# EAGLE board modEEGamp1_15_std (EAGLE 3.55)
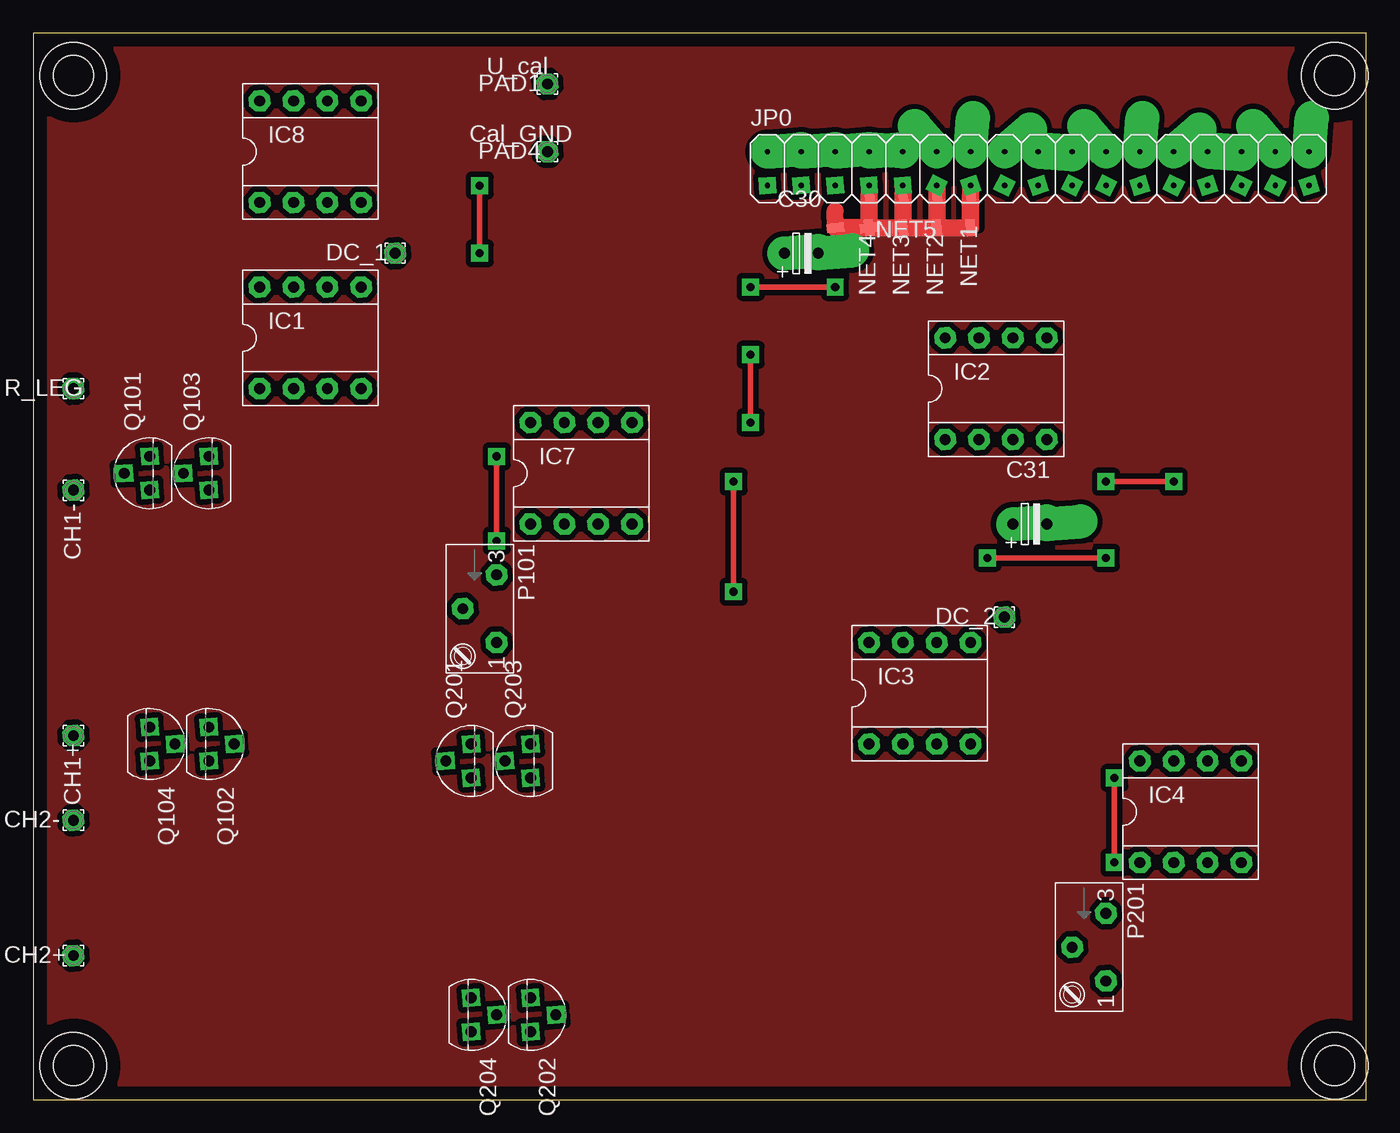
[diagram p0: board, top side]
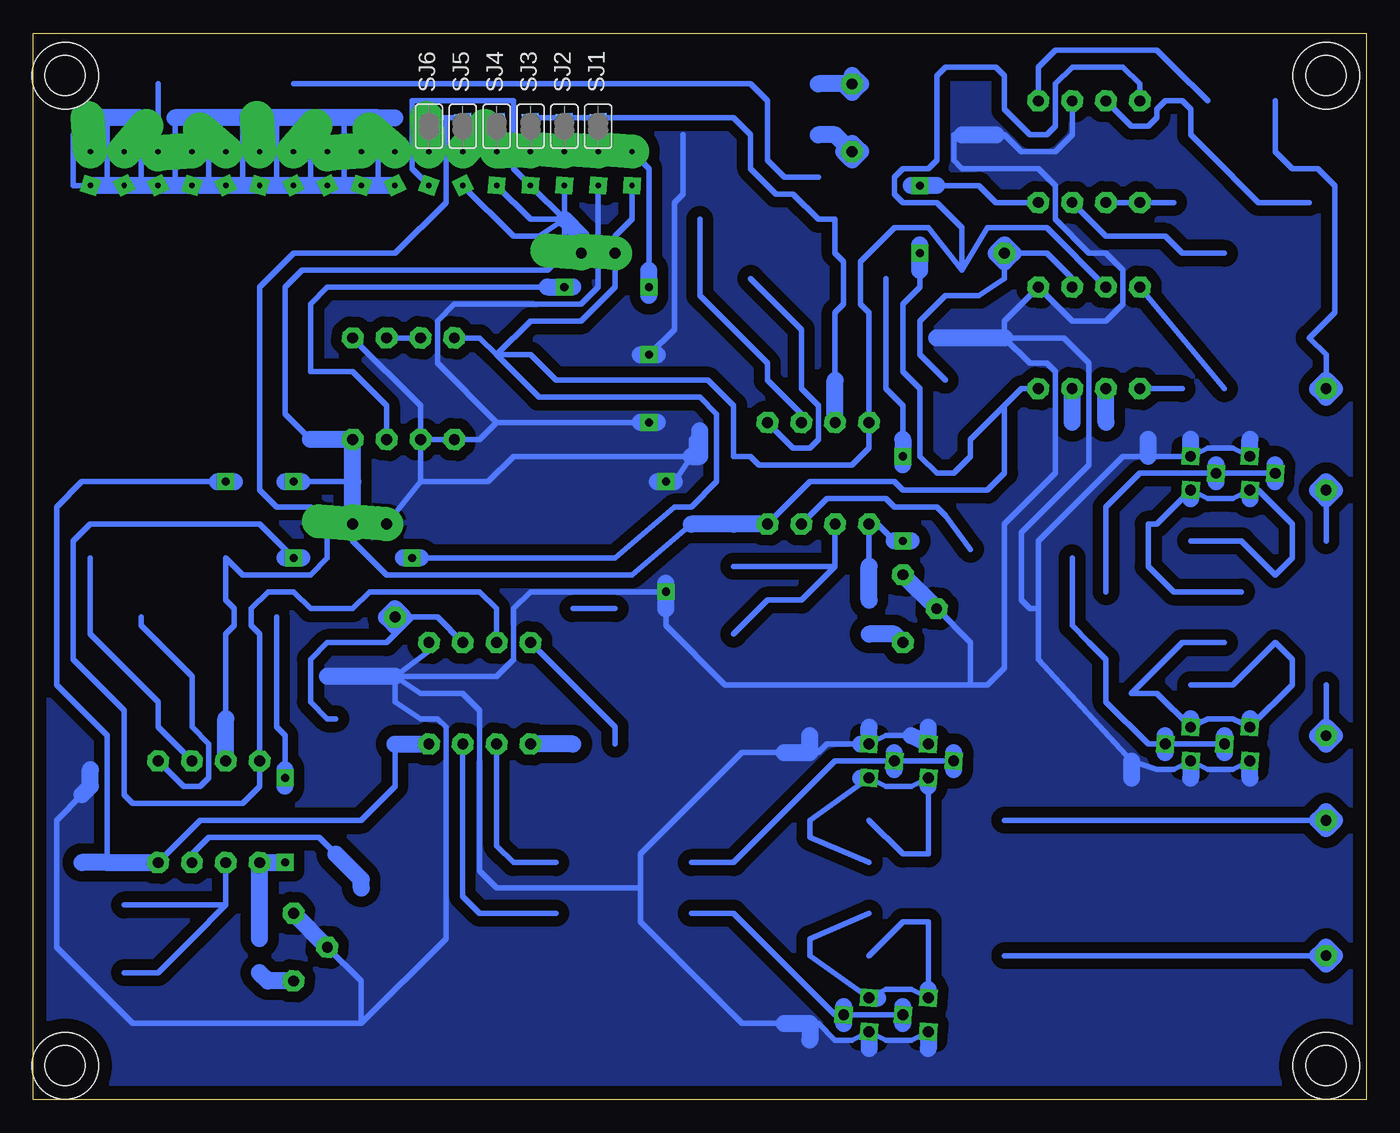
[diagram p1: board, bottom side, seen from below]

Size 100 x 80 mm. Coordinates in mm from the lower left corner, seen from the top.
Outline: 0,0 100,0 100,80 0,80 0,0
Copper layers used: Top, Bottom
Holes 3 mm at 3.01,2.54 3.01,76.83 97.62,2.54 97.62,76.83
Holes 5 mm at 3.01,76.83 97.62,76.83 3.01,2.54 97.62,2.54

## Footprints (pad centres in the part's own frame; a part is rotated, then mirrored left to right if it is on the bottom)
-2,5 = drill 0.813 pad 2.54 offset:  -1.27,0;  1.27,0
6/0,8 = drill 0.813 pad 1.6 octagon:  0,0
P-08 = drill 0.813 pad 1.6 octagon:  -3.81,-3.81;  -1.27,-3.81;  3.81,3.81;  1.27,3.81;  1.27,-3.81;  3.81,-3.81;  -1.27,3.81;  -3.81,3.81
17Y = drill 0.406 pad 1.27 square:  -20.32,-1.27;  -17.78,-1.27;  -15.24,-1.27;  -12.7,-1.27;  -10.16,-1.27;  -7.62,-1.27;  -5.08,-1.27;  -2.54,-1.27;  0,-1.27;  2.54,-1.27;  5.08,-1.27;  7.62,-1.27;  10.16,-1.27;  12.7,-1.27;  15.24,-1.27;  17.78,-1.27;  20.32,-1.27 | drill 0.406 pad 2.54 offset:  -20.32,1.27;  -17.78,1.27;  -15.24,1.27;  -12.7,1.27;  -10.16,1.27;  -7.62,1.27;  -5.08,1.27;  -2.54,1.27;  0,1.27;  2.54,1.27;  5.08,1.27;  7.62,1.27;  10.16,1.27;  12.7,1.27;  15.24,1.27;  17.78,1.27;  20.32,1.27
TCPL_T = smd 0.635 x 1.27 rotated 97:  -1.27,0;  1.27,0
4Y = drill 0.813 pad 1.6 octagon:  2.54,1.27;  -2.54,1.27;  0,-1.27
92 = drill 0.813 pad 1.27 square:  1.27,0;  0,1.905;  -1.27,0
5X5 = smd 0.635 x 1.27 rotated 4.3:  -0.635,0 | smd 0.635 x 1.27 rotated 4.4:  0.635,0

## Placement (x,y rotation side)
C3  10nF  [5-Y]  79.21,52.07 270 top
C13  0.1uFcer  [5-Y]  73.5,46.35 0 top
C21  0.1uFcer  [5-Y]  65.24,53.34 90 top
C22  10nFcer  [5-Y]  57.62,66.04 0 top
C28  1nF_200V  [5-Y]  9.36,71.12 0 top
C30  47æ  [-2,5]  57.62,63.5 0 top
C31  47æ_tant_500mO  [-2,5]  74.77,43.18 0 top
C36  1n_200V  [5-Y]  9.36,74.93 0 top
C41  0.1uFcer  [5-Y]  27.77,69.85 90 top
C42  0.1uFcer  [5-XY]  30.31,74.93 90 top
C101  10pF_cer  [5-Y]  6.82,36.83 90 top
C102  100pF_cer  [5-Y]  17.61,27.94 270 top
C103  100pF_cer  [5-Y]  16.34,45.72 270 top
C104  0.1uFcer  [5-Y]  27.14,54.61 90 top
C105  0.1uFcer  [5-Y]  30.31,59.69 270 top
C106  1æF  [5-10C]  31.58,48.9 90 top
C107  1nF  [5-Y]  39.84,37.47 180 top
C108  1uF  [5-10C]  41.11,61.59 0 top
C109  1nF  [5-Y]  42.38,53.98 180 top
C110  0.1uFcer  [5-Y]  50.63,45.72 90 top
C111  0.1uFcer  [5-X]  47.46,45.72 90 top
C201  10pF_cer  [5-Y]  32.85,15.88 90 top
C202  100pF_cer  [5-Y]  41.74,8.26 270 top
C203  100pF_cer  [5-Y]  41.74,23.5 270 top
C204  0.1uFcer  [5-Y]  72.86,29.21 90 top
C205  0.1uFcer  [5-Y]  76.03,34.29 270 top
C206  1æF  [5-10C]  77.3,23.5 90 top
C207  1nF  [5-Y]  85.56,12.06 180 top
C208  1uF  [5-10C]  86.83,36.2 0 top
C209  1nF  [5-Y]  88.1,28.57 180 top
C210  0.1uFcer  [5-X]  96.36,20.32 90 top
C211  0.1uFcer  [5-X]  93.18,20.32 90 top
CH1+  [6/0,8]  3.01,27.3 90 top
CH1-  [6/0,8]  3.01,45.72 90 top
CH2+  [6/0,8]  3.01,10.79 0 top
CH2-  [6/0,8]  3.01,20.95 0 top
DC_1  [6/0,8]  27.14,63.5 0 top
DC_2  [6/0,8]  72.86,36.2 0 top
IC1  INA114BP  [P-08]  20.79,57.15 0 top
IC2  TLC277CP  [P-08]  72.22,53.34 0 top
IC3  INA114BP  [P-08]  66.51,30.48 0 top
IC4  TLC277P  [P-08]  86.83,21.59 0 top
IC7  TLC277P  [P-08]  41.11,46.99 0 top
IC8  TLC277P  [P-08]  20.79,71.12 0 top
JP0  PINHD-2X17  [17Y]  75.4,69.85 0 top
NET1  NETCPL_T  [TCPL_T]  70.32,66.67 90 top
NET2  NETCPL_T  [TCPL_T]  67.78,66.67 90 top
NET3  NETCPL_T  [TCPL_T]  65.24,66.67 90 top
NET4  NETCPL_T  [TCPL_T]  62.7,66.67 90 top
NET5  NETCPL_T  [TCPL_T]  61.43,65.41 180 top
P101  10k  [4Y]  33.49,36.83 270 top
P201  10k  [4Y]  79.21,11.43 270 top
PAD1  U_cal  [6/0,8]  38.57,76.2 0 top
PAD4  Cal_GND  [6/0,8]  38.57,71.12 0 top
Q101  BC547  [92]  8.73,46.99 90 top
Q102  BC547  [92]  13.17,26.67 270 top
Q103  BC557  [92]  13.17,46.99 90 top
Q104  BC557  [92]  8.73,26.67 270 top
Q201  BC547  [92]  32.85,25.4 90 top
Q202  BC547  [92]  37.3,6.35 270 top
Q203  BC557  [92]  37.3,25.4 90 top
Q204  BC557  [92]  32.85,6.35 270 top
R25  510k  [10]  4.28,62.23 90 top
R26  10k  [10]  46.19,72.39 0 top
R27  10k  [10]  14.44,72.39 270 top
R33  2.0M_1%  [10Q]  85.56,76.2 0 top
R34  100_1%  [10Q]  46.19,69.22 180 top
R42  10k  [10Q]  46.19,76.2 0 top
R101  2k2  [10]  8.09,41.91 0 top
R102  2k2  [10]  8.09,31.11 0 top
R103  2k2  [10]  14.44,38.1 0 top
R104  2k2  [10]  15.71,34.29 0 top
R105  2k2  [10]  19.52,45.72 90 top
R106  2k2  [10]  22.06,45.72 90 top
R107  2k7_1%  [10Q]  13.81,58.42 90 top
R108  2k7_1%  [10Q]  10.63,58.42 90 top
R109  1meg  [10Q]  29.68,36.2 90 top
R110  1k  [10]  42.38,34.92 0 top
R111  200k  [10Q]  42.38,40.01 180 top
R112  1meg  [10Q]  37.3,57.15 0 top
R113  1k  [10]  50,55.24 90 top
R114  27k  [10Q]  44.92,66.04 180 top
R201  2k2  [10]  32.22,20.95 0 top
R202  2k2  [10]  32.22,10.79 0 top
R203  2k2  [10]  42.38,17.78 0 top
R204  2k2  [10]  42.38,13.97 0 top
R205  2k2  [10]  55.71,17.78 0 top
R206  2k2  [10]  55.71,13.97 0 top
R207  2k7_1%  [10Q]  59.52,31.75 90 top
R208  2k7_1%  [10Q]  56.35,31.75 90 top
R209  1meg  [10Q]  75.4,10.79 90 top
R210  1k  [10]  88.1,9.53 0 top
R211  200k  [10Q]  88.1,14.61 180 top
R212  1meg  [10Q]  83.02,31.75 0 top
R213  1k  [10]  95.72,29.84 90 top
R214  27k  [10Q]  90.64,40.64 180 top
R_LEG  [6/0,8]  3.01,53.34 0 top
SJ1  SJ  [5X5]  57.62,73.03 90 bottom
SJ2  SJ  [5X5]  60.16,73.03 90 bottom
SJ3  SJ  [5X5]  62.7,73.03 90 bottom
SJ4  SJ  [5X5]  65.24,73.03 90 bottom
SJ5  SJ  [5X5]  67.78,73.03 90 bottom
SJ6  SJ  [5X5]  70.32,73.03 90 bottom

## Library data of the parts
C3 C13 C21 C22 C28 C30 C31 C36 C41 C42 C101-C111 C201-C211 R25-R27 R33 R34 R42 R101-R114 R201-R214 = DISCRETE
CH1+ CH1- CH2+ CH2- DC_1 DC_2 PAD1 PAD4 R_LEG = WIREPAD
IC1-IC4 IC7 IC8 = BURR
JP0 = PINHEAD
NET1-NET5 = SPECIAL
P101 P201 = TRIMPOT
Q101 Q102 Q201 Q202 = NPN
Q103 Q104 Q203 Q204 = pnp
SJ1-SJ6 = JUMPER

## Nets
2.0V: C3. IC2. JP0.
+5V/2: C21. C22. C30. C42. C105. C111. C205. C211. IC1. IC2. IC3. IC4. IC7. IC8. JP0.
+5V/3: JP0.
ADIN0: C109. IC7. R114. SJ1. SJ2. SJ3.
ADIN1: C209. IC4. R214. SJ4. SJ5. SJ6.
AGND: C3. C13. C22. C30. C31. C41. C104. C110. C111. C204. C210. C211. IC1. IC2. IC3. IC4. IC7. IC8. JP0. NET1. NET2. NET3. NET4. NET5.
AGND2: NET1. NET2. NET3. NET4. NET5.
GND2: JP0.
N$1: IC3. R207.
N$2: IC3. R208.
N$3: R207. R208.
N$4: C206. DC_2. IC3.
N$5: IC3. R205.
N$6: CH1-. R101.
N$7: IC3. R206.
N$8: Q201. Q203. R203. R205.
N$9: C201. C203. Q201. Q203. R201. R203.
N$10: Q202. Q204. R204. R206.
N$11: CH1+. R102.
N$12: IC8. R107. R108.
N$13: C201. C202. Q202. Q204. R202. R204.
N$14: IC1. R107.
N$15: CH2-. R201.
N$16: CH2+. R202.
N$17: C206. IC4. R209.
N$18: C207. IC4. R210. R211.
N$19: P201. R210.
N$20: IC1. R108.
N$21: IC1. R105.
N$22: C207. C208. IC4. R211.
N$23: C208. IC4. R212.
N$24: C209. IC4. R213. R214.
N$25: C106. DC_1. IC1.
N$26: JP0. SJ1.
N$27: IC1. R106.
N$28: C106. IC7. R109.
N$29: Q101. Q103. R103. R105.
N$30: PAD4. R26.
N$31: JP0. SJ2.
N$32: C101. C103. Q101. Q103. R101. R103.
N$33: C28. IC8. R25.
N$34: R33. R34. R42.
N$35: JP0. SJ3.
N$36: JP0. SJ4.
N$37: JP0. SJ5.
N$38: C107. IC7. R110. R111.
N$39: Q102. Q104. R104. R106.
N$40: P101. R110.
N$41: C36. IC8. R27.
N$42: C107. C108. IC7. R111.
N$43: C101. C102. Q102. Q104. R102. R104.
N$44: JP0. SJ6.
N$48: PAD1. R42.
N$50: C108. IC7. R112.
N$51: C109. IC7. R113. R114.
N$52: IC8. R27.
N$53: IC2.
PWM: JP0. R33.
R_LEG: C28. C36. R25. R_LEG.
VREF/2: C13. C21. C31. C41. C42. C102. C103. C104. C105. C110. C202. C203. C204. C205. C210. IC1. IC2. IC3. IC8. JP0. P101. P201. Q101. Q102. Q103. Q104. Q201. Q202. Q203. Q204. R26. R34. R109. R112. R113. R209. R212. R213.

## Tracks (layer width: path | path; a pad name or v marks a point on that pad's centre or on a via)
2.0V  (via drill 0.61 pad 1.27)
  Top 0.406: v53.81,60.96 v60.16,60.96
  Bottom 0.406: 73.5,49.53 73.5,52.07 76.03,54.61 79.21,54.61 79.21,59.69 77.94,60.96 61.43,60.96 v60.16,60.96 | v53.81,60.96 53.81,62.23 53.81,69.85 55.08,71.12
  Bottom 1.27: 53.81,60.33 53.81,62.23 | 61.43,60.96 59.52,60.96
+5V/2  (via drill 0.61 pad 1.27)
  Top 0.406: v71.59,40.64 v80.48,40.64
  Bottom 0.406: 55.08,68.58 55.08,66.04 56.35,64.77 56.35,63.5 56.35,60.96 58.89,58.42 62.7,58.42 65.24,55.88 | 19.52,60.96 23.96,65.41 28.41,65.41 30.31,62.23 | 65.24,55.88 66.51,57.15 IC2. | IC8. 16.98,76.2 18.25,77.47 22.06,77.47 23.33,76.2 23.33,73.03 23.96,72.39 25.23,72.39 27.14,74.3 27.14,76.83 27.77,77.47 30.31,77.47 31.58,77.47 32.22,76.83 32.22,70.48 32.85,69.85 34.76,69.85 35.39,69.22 35.39,67.94 34.76,67.31 32.22,67.31 30.31,65.41 30.31,62.23 | 30.31,62.23 32.85,65.41 35.39,65.41 37.94,62.87 37.94,59.69 37.3,59.05 IC7. 37.3,48.9 38.57,47.62 45.55,47.62 46.19,48.26 47.46,48.26 47.46,52.07 49.37,53.98 60.8,53.98 62.7,55.88 65.24,55.88 | 65.24,34.29 65.24,36.83 66.51,38.1 74.77,38.1 76.03,36.83 79.21,36.83 80.48,38.1 82.39,38.1 83.66,36.83 83.66,35.56 83.02,34.92 IC4. 83.02,23.5 84.29,22.23 92.55,22.23 93.18,22.86 93.18,29.21 96.99,33.02 96.99,41.91 95.72,43.18 83.02,43.18 v80.48,40.64 | 65.24,55.88 62.06,52.7 50,52.7 48.73,51.44 48.73,46.35 50.63,44.45 51.91,44.45 56.35,40.64 v71.59,40.64
  Bottom 1.27: 70.95,40.64 v71.59,40.64 72.22,40.64 | 79.84,40.64 v80.48,40.64 81.11,40.64
ADIN0
  Bottom 0.406: SJ3. SJ2. SJ1. 47.46,73.66 46.19,72.39 46.19,69.85 44.28,67.94 43.02,67.94 41.11,66.04 39.84,66.04 39.84,63.5 39.2,62.87 39.2,59.69 39.84,59.05 39.84,53.98 39.84,50.8
  Bottom 1.27: 39.84,50.8 39.84,53.98
ADIN1
  Bottom 0.406: SJ4. SJ5. 69.05,73.66 | 69.05,73.66 SJ6. | 69.05,73.66 69.05,67.31 72.86,63.5 80.48,63.5 83.02,60.96 83.02,45.72 81.75,44.45 79.21,44.45 77.94,43.18 77.94,40.64 79.21,39.37 84.29,39.37 85.56,40.64 85.56,37.47 84.92,36.83 84.92,35.56 85.56,34.92 85.56,28.57 85.56,25.4
  Bottom 1.27: 85.56,25.4 85.56,28.57
AGND  (via drill 0.61 pad 1.27)
  Top 0.406: v33.49,63.5 v33.49,68.58 | v80.48,46.35 v85.56,46.35 | 70.32,68.58 NET1.
  Top 1.27: 62.7,68.58 NET4. | 65.24,68.58 NET3. | 67.78,68.58 NET2. | 70.32,68.58 NET1. | NET5. 60.16,66.04 60.16,66.67
  Bottom 0.406: 67.78,68.58 63.97,64.77 62.06,64.77 60.16,66.04 | 65.24,68.58 62.7,66.04 60.16,66.04 | 60.16,66.04 60.16,68.58 | 60.16,66.04 62.7,68.58 63.97,69.85 63.97,74.93 71.59,74.93 71.59,69.85 70.32,68.58 | 60.16,66.04 60.16,63.5 61.43,62.23 79.84,62.23 81.11,60.96 81.11,51.44 79.21,49.53 | 24.6,67.31 27.77,67.31 29.04,68.58 32.22,68.58 v33.49,68.58 | 24.6,53.34 25.87,53.34 27.14,52.07 | 27.14,52.07 27.14,46.99 28.41,45.72 34.76,45.72 35.39,46.35 41.74,46.35 44.92,43.18 47.46,43.18 50.63,43.18 55.08,39.37 73.5,39.37 76.03,41.91 C31. | v33.49,63.5 33.49,62.23 33.49,60.96 34.76,59.69 34.76,54.61 33.49,53.34 33.49,48.26 32.22,46.99 30.95,46.99 29.68,48.26 29.68,49.53 27.14,52.07 | 93.18,17.78 90.64,17.78 87.47,20.95 75.4,20.95 72.86,23.5 72.86,26.67 | 76.03,46.35 79.84,46.35 | 86.19,46.35 96.36,46.35 98.26,44.45 98.26,31.11 94.45,27.3 94.45,17.78
  Bottom 1.27: C31. 76.03,46.35 76.03,49.53 79.21,49.53 | 72.86,26.67 70.32,26.67 | 50.63,43.18 47.46,43.18 44.92,43.18 | 96.36,17.78 94.45,17.78 93.18,17.78 90.64,17.78 | 32.22,68.58 34.12,68.58 | 33.49,62.23 33.49,64.14 | 79.84,46.35 v80.48,46.35 81.11,46.35 | 86.19,46.35 v85.56,46.35 84.92,46.35 | C30. 58.89,64.77 60.16,66.04
AGND2
  Top 1.27: 62.7,65.41 65.24,65.41 67.78,65.41 70.32,65.41
  pour Top (isolate 0.406, no thermals): 0.47,80.01 99.53,80.01 99.53,0 0.47,0
GND2
  Bottom 0.406: 74.13,68.58 74.13,73.66 | 76.67,73.66 76.67,68.58 | 79.21,73.66 79.21,68.58 | 81.75,73.66 81.75,68.58 | 84.29,73.66 84.29,68.58 | 86.83,73.66 86.83,68.58 | 89.37,73.66 89.37,68.58 | 91.91,68.58 91.91,73.66 | 94.45,73.66 94.45,68.58 | 95.72,73.66 96.99,72.39 96.99,68.58 95.72,68.58
  Bottom 1.27: 72.86,68.58 74.13,68.58 75.4,68.58 76.67,68.58 77.94,68.58 79.21,68.58 80.48,68.58 81.75,68.58 83.02,68.58 84.29,68.58 85.56,68.58 86.83,68.58 88.1,68.58 89.37,68.58 90.64,68.58 91.91,68.58 93.18,68.58 94.45,68.58 95.72,68.58 | 72.86,73.66 74.13,73.66 76.67,73.66 79.21,73.66 81.75,73.66 84.29,73.66 86.83,73.66 89.37,73.66 | 91.91,73.66 94.45,73.66 95.72,73.66
N$1
  Bottom 1.27: 59.52,26.67 62.7,26.67
N$2
  Bottom 0.406: 56.35,26.67 56.35,27.94 IC3.
N$3
  Bottom 0.406: 56.35,36.83 59.52,36.83
N$4
  Bottom 0.406: 77.3,28.57 77.94,28.57 79.21,29.84 79.21,33.02 77.94,34.29 73.5,34.29 71.59,36.2 | 71.59,36.2 69.69,36.2 67.78,34.29 | 71.59,36.2 72.22,36.2 DC_2.
  Bottom 1.27: 72.22,36.2 72.86,36.83 73.5,36.2 72.86,35.56
N$5
  Bottom 0.406: 60.8,17.78 63.97,17.78 65.24,19.05 65.24,26.67
N$6
  Bottom 0.406: 3.01,41.91 3.01,46.35 CH1-.
  Bottom 1.27: 3.01,46.35 3.64,45.72 3.01,45.09 2.38,45.72 3.01,46.35
N$7
  Bottom 0.406: 60.8,13.97 66.51,13.97 67.78,15.24 67.78,26.67
N$8
  Bottom 0.406: 30.95,25.4 35.39,25.4 39.84,25.4 47.46,17.78 50.63,17.78
  Bottom 1.27: 30.95,26.04 30.95,25.4 30.95,24.77 | 35.39,26.04 35.39,25.4 35.39,24.77
N$9
  Bottom 0.406: 37.3,20.95 34.76,18.41 32.85,18.41 32.85,23.5 | Q201. 34.12,23.5 36.03,23.5 Q203. 41.74,20.95 41.74,19.68 37.3,17.78
  Bottom 1.27: 32.85,23.5 Q201. | Q203. 37.94,24.13
N$10
  Bottom 0.406: 34.76,6.35 39.2,6.35 39.84,6.35 47.46,13.97 50.63,13.97
  Bottom 1.27: 34.76,6.99 34.76,6.35 34.76,5.71 | 39.2,6.99 39.2,6.35 39.2,5.71
N$11
  Bottom 0.406: CH1+. 3.01,27.94 3.01,31.11
  Bottom 1.27: 2.38,27.3 3.01,27.94 3.64,27.3 3.01,26.67 2.38,27.3
N$12
  Bottom 0.406: 10.63,63.5 13.81,63.5 15.08,64.77 19.52,64.77 22.06,67.31
N$13
  Bottom 0.406: 37.3,10.79 34.76,13.34 32.85,13.34 32.85,8.26 | Q204. 34.12,8.26 36.03,8.26 Q202. 41.74,10.79 41.74,12.06 37.3,13.97
  Bottom 1.27: Q204. 32.85,8.26 | Q202. 36.66,7.62
N$14
  Bottom 0.406: 13.81,53.34 16.98,53.34
N$15
  Bottom 0.406: CH2-. 3.64,20.95 27.14,20.95
  Bottom 1.27: 3.01,21.59 3.64,20.95 3.01,20.32 2.38,20.95 3.01,21.59
N$16
  Bottom 0.406: CH2+. 3.64,10.79 27.14,10.79
  Bottom 1.27: 3.01,11.43 3.64,10.79 3.01,10.16 2.38,10.79 3.01,11.43
N$17
  Bottom 0.406: 77.3,18.41 78.58,19.68 86.83,19.68 88.1,18.41 88.1,17.78
  Bottom 1.27: 75.4,15.88 75.4,16.51 77.3,18.41
N$18
  Bottom 0.406: 93.18,9.53 90.64,9.53 88.1,12.06 85.56,14.61 | 85.56,14.61 85.56,17.78 | 85.56,14.61 93.18,14.61
N$19
  Bottom 1.27: 83.02,9.53 82.39,8.89 80.48,8.89
N$20
  Bottom 0.406: 10.63,53.34 IC1.
N$21
  Bottom 0.406: 19.52,50.8 19.52,53.34
  Bottom 1.27: 19.52,50.8 19.52,53.34
N$22  (via drill 0.61 pad 1.27)
  Top 0.406: v81.11,17.78 v81.11,24.13
  Bottom 0.406: 81.75,36.2 81.75,27.94 81.11,27.3 81.11,24.77 v81.11,24.13 | v81.11,17.78 83.02,17.78 83.02,14.61 83.02,12.06
  Bottom 1.27: v81.11,17.78 83.02,17.78 83.02,14.61 83.02,12.06 | 81.11,24.77 81.11,23.5
N$23
  Bottom 0.406: 91.91,36.2 91.91,35.56 88.1,31.75 88.1,27.94 86.83,26.67 86.83,24.13 87.47,23.5 88.73,23.5 90.64,25.4
N$24
  Bottom 0.406: 95.72,40.64 95.72,34.92 90.64,29.84 90.64,28.57 90.64,27.94 88.1,25.4
N$25
  Bottom 0.406: 22.06,60.96 22.06,61.59 23.96,63.5 26.5,63.5 | 27.14,62.87 27.14,61.59 29.04,60.33 31.58,60.33 33.49,58.42 33.49,55.88 31.58,53.98
  Bottom 1.27: DC_1. 27.14,62.87 | 26.5,63.5 DC_1. | DC_1. 27.77,63.5 | 26.5,63.5 27.14,64.14 27.77,63.5 | 27.14,62.87 27.77,63.5 | 26.5,63.5 27.14,62.87
N$26
  Bottom 0.406: 57.62,71.12 57.62,72.39
N$27
  Bottom 0.406: 22.06,50.8 22.06,53.34
  Bottom 1.27: 22.06,50.8 22.06,53.34
N$28
  Bottom 0.406: 29.68,41.27 31.58,43.81 32.22,44.45 35.39,44.45 36.03,45.09 40.48,45.09 42.38,43.18
N$29
  Bottom 0.406: 6.82,46.99 11.27,46.99 16.98,46.99 19.52,44.45 19.52,40.64 19.52,38.1
  Bottom 1.27: 6.82,47.62 6.82,46.99 6.82,46.35 | 11.27,47.62 11.27,46.99 11.27,46.35
N$30
  Bottom 0.406: PAD4. 39.2,71.75
  Bottom 1.27: 37.94,71.12 PAD4. | 37.94,71.12 38.57,71.75 39.2,71.12 38.57,70.48 37.94,71.12 | 41.11,72.39 39.84,72.39 39.2,71.75
N$31
  Bottom 0.406: 60.16,71.12 60.16,72.39
N$32
  Bottom 0.406: 13.17,41.91 9.36,41.91 6.82,39.37 5.55,40.64 5.55,43.18 8.09,45.72 Q101. 10,45.09 11.9,45.09 Q103. 15.71,43.18 16.34,43.18 16.34,40.01 14.44,38.1 9.36,38.1
  Bottom 1.27: Q101. 8.73,45.09 | Q103. 13.17,45.09
N$33
  Bottom 0.406: 19.52,74.93 17.61,73.03 16.34,73.03 15.71,73.66 15.71,74.3 15.08,74.93 13.81,74.93 13.17,74.3 13.17,72.39 11.9,71.12 8.09,67.31 4.28,67.31
N$34
  Bottom 0.406: 41.11,69.22 43.65,69.22 44.92,70.48 44.92,74.93 46.19,76.2 51.27,76.2 80.48,76.2
N$35
  Bottom 0.406: 62.7,71.12 62.7,72.39
N$36
  Bottom 0.406: 65.24,71.12 65.24,72.39
N$37
  Bottom 0.406: 67.78,71.12 67.78,72.39
N$38
  Bottom 0.406: 39.84,40.01 39.84,43.18 | 39.84,40.01 47.46,40.01 | 39.84,40.01 42.38,37.47 44.92,37.47 47.46,34.92
N$39
  Bottom 0.406: 10.63,26.67 15.08,26.67 16.34,26.67 19.52,29.84 19.52,33.02 20.79,34.29 22.06,35.56 22.06,40.64
  Bottom 1.27: 10.63,27.3 10.63,26.67 10.63,26.04 | 15.08,27.3 15.08,26.67 15.08,26.04
N$40
  Bottom 1.27: 34.76,34.29 35.39,34.92 37.3,34.92
N$41
  Bottom 0.406: 24.6,74.93 24.6,77.47 23.33,78.74 15.71,78.74 14.44,77.47 11.9,74.93
N$42  (via drill 0.61 pad 1.27)
  Top 0.406: v34.76,41.91 v34.76,48.26
  Bottom 0.406: 37.3,37.47 37.3,40.01 37.3,43.18 36.66,43.18 35.39,41.91 v34.76,41.91 | 36.03,61.59 36.03,53.34 34.76,52.07 34.76,49.53 v34.76,48.26
  Bottom 1.27: 37.3,37.47 37.3,40.01 | 34.76,49.53 34.76,47.62 | 35.39,41.91 34.12,41.91
N$43
  Bottom 0.406: 13.17,31.11 10,31.11 6.82,34.29 5.55,33.02 5.55,31.11 Q104. 10,28.57 11.9,28.57 Q102. 15.71,30.48 17.61,30.48 13.81,34.29 10.63,34.29
  Bottom 1.27: Q104. 8.73,28.57 | Q102. 13.17,28.57
N$44
  Bottom 0.406: 70.32,71.12 70.32,72.39
N$48
  Bottom 1.27: 39.2,76.2 PAD1. 38.57,76.83 37.94,76.2 38.57,75.56 39.2,76.2 | 39.2,76.2 41.11,76.2
N$50
  Bottom 0.406: 46.19,61.59 42.38,57.78 42.38,57.15 42.38,53.34 41.11,52.07 41.11,49.53 41.74,48.9 43.02,48.9 44.92,50.8
N$51
  Bottom 0.406: 50,66.04 50,60.33 44.92,55.24 44.92,53.98 42.38,51.44 42.38,50.8
N$52
  Bottom 0.406: 14.44,67.31 16.98,67.31 19.52,67.31
N$53
  Bottom 0.406: 70.95,57.15 73.5,57.15
PWM
  Bottom 0.406: 90.64,71.12 90.64,76.2
R_LEG
  Bottom 0.406: 6.82,74.93 6.82,71.12 5.55,69.85 3.64,69.85 2.38,68.58 2.38,59.05 4.28,57.15 3.01,55.88 3.01,53.98 R_LEG.
  Bottom 1.27: 2.38,53.34 3.01,53.98 3.64,53.34 3.01,52.7 2.38,53.34
VREF/2  (via drill 0.61 pad 1.27)
  Top 0.406: v52.54,38.1 v52.54,46.35 | v53.81,50.8 v53.81,55.88
  Bottom 0.406: 70.95,46.35 73.5,43.18 | 70.95,46.35 70.95,49.53 | 70.95,49.53 68.41,49.53 66.51,49.53 65.24,50.8 | 70.95,49.53 70.95,52.07 76.03,57.15 | 8.73,48.26 10,48.9 11.9,48.9 13.17,48.26 16.34,48.26 18.25,48.26 24.6,41.91 24.6,36.83 | 24.6,36.83 24.6,33.02 17.61,25.4 15.71,24.77 14.44,24.77 13.17,25.4 11.9,24.77 10,24.77 8.73,25.4 | 27.14,57.15 30.31,57.15 32.22,57.15 | 27.14,57.15 22.7,57.15 20.79,55.24 20.79,47.62 25.87,42.55 25.87,37.47 25.23,36.83 24.6,36.83 | 22.06,74.93 22.06,72.39 23.33,71.12 25.87,71.12 27.14,72.39 27.77,72.39 30.31,72.39 30.95,72.39 30.95,70.48 30.31,69.85 24.6,69.85 23.33,68.58 23.33,66.04 20.79,63.5 19.52,63.5 18.25,62.23 18.25,59.69 19.52,58.42 22.06,58.42 24.6,60.96 27.14,58.42 27.14,57.15 | 57.62,68.58 57.62,60.96 58.89,59.69 68.41,59.69 69.69,58.42 69.69,55.24 65.24,50.8 | 34.76,39.37 P101. 29.68,34.29 29.68,31.11 | 29.68,31.11 28.41,31.11 27.14,32.38 27.14,43.18 23.33,46.99 23.33,54.61 23.96,55.24 25.23,55.24 27.14,57.15 | 50.63,48.26 63.97,48.26 65.88,46.35 70.95,46.35 | 50.63,48.26 50.63,49.53 50,50.16 | 29.68,31.11 48.09,31.11 52.54,35.56 52.54,36.83 | v52.54,46.35 51.91,46.35 50.63,48.26 | 77.94,31.75 76.03,31.75 72.86,31.75 | 72.86,31.75 70.32,33.66 70.32,34.29 | 37.3,26.67 36.03,27.3 34.12,27.3 | 41.74,26.04 41.11,26.04 40.48,26.67 37.94,26.67 | 32.85,5.08 34.12,4.45 36.03,4.45 37.3,5.08 38.57,4.45 39.84,4.45 41.11,5.71 41.74,5.71 | 75.4,5.71 75.4,8.89 P201. 80.48,13.97 | 75.4,5.71 92.55,5.71 98.26,11.43 98.26,20.95 96.36,22.86 | 72.86,31.75 70.95,30.48 67.78,30.48 66.51,29.21 66.51,17.14 65.24,15.88 54.45,15.88 | 43.65,26.04 46.82,26.04 54.45,18.41 54.45,15.88
  Bottom 0.406: 54.45,15.88 54.45,13.34 46.82,5.71 43.65,5.71 | 72.86,31.75 72.86,29.84 70.95,28.57 69.69,28.57 69.05,27.94 69.05,12.06 75.4,5.71 | 65.24,50.8 54.45,50.8 | 51.27,72.39 51.27,69.22 51.27,67.94 51.91,67.31 51.91,57.78 v53.81,55.88 | 72.86,31.75 65.24,31.75 63.97,33.02 63.97,36.83 62.7,38.1 v52.54,38.1
  Bottom 1.27: 27.14,57.15 30.31,57.15 32.22,57.15 | 30.31,72.39 27.77,72.39 | 50,50.16 50,48.26 50.63,48.26 | P101. 34.76,39.37 | 72.86,31.75 76.03,31.75 77.94,31.75 | 95.72,24.77 95.72,23.5 96.36,22.86 | P201. 80.48,13.97 | 54.45,55.88 v53.81,55.88 53.17,55.88 | 54.45,50.8 v53.81,50.8 53.17,50.8 | 51.91,46.35 53.17,46.35 | 52.54,36.83 v52.54,38.1 52.54,38.73 | 32.85,27.94 32.85,26.67 34.12,27.3 | 37.3,27.94 37.3,26.67 37.94,26.67 | 43.65,26.04 41.74,26.04 41.74,27.3 | 32.85,5.08 32.85,3.81 | 37.3,5.08 37.3,3.81 | 8.73,24.13 8.73,25.4 | 13.17,25.4 13.17,24.13 | 8.73,48.26 8.73,49.53 | 13.17,48.26 13.17,49.53 | 16.34,48.26 16.34,49.53 | 17.61,25.4 17.61,24.13 | 41.74,4.45 41.74,5.71 43.65,5.71
  pour Bottom (isolate 0.813): 0.47,80.01 99.53,80.01 99.53,0 0.47,0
